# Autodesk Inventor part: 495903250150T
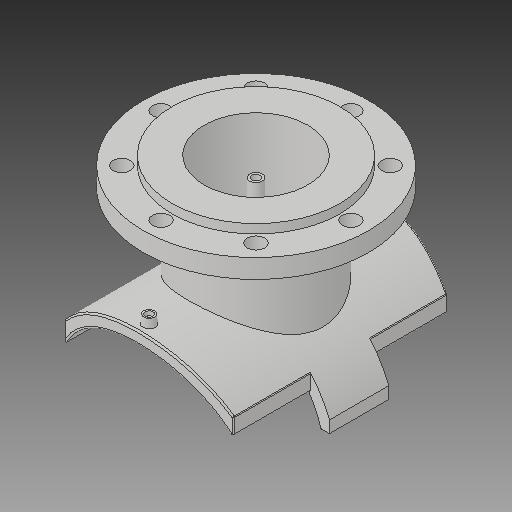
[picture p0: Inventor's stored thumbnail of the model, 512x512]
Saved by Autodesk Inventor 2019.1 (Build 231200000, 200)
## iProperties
Created: 2017-10
Part Number: 495903250150T
Material: Generic
Description: PLASSON FLANGED BRANCH SADDLE 250x150
Document SubType Name: Modeling
Designer: KIM
Mass: 2339.99 g
Surface Area: 3251.55 cm^2
Volume: 2339.99 cm^3
Density: 1 g/cm^3
Appearance: Default
Author: KIM
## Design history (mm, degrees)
derived "495904_495903.ipt"
feature "Solid1::495904_495903.ipt"
feature "Solid2::495904_495903.ipt"
tag "TaggingFeature1"
body "Solid1"
other parameters: "d1" = 15, "d2" = 213.3, "d4" = 0, "d6" = 75, "d7" = 0, "d12" = 150.6, "d13" = 14, "d14" = 135, "d16" = 5 deg, "d18" = 4, "d19" = 14, "d20" = 0, "d21" = 3, "d22" = 0, "d23" = 272, "d36" = 135, "d38" = 0, "d39" = 2, "d41" = 131, "d42" = 212, "d43" = 285, "d44" = 105.6, "d46" = 169.6, "d47" = 16, "d48" = 10.4, "d49" = 92.4, "d51" = 255, "d53" = 0, "d54" = 22, "d57" = 0, "d59" = 360 deg, "d61" = 24, "d63" = 0, "d66" = 132, "d67" = 15, "d68" = 66, "d70" = 0, "d71" = 2, "d72" = 237, "d_1" = 212, "B_" = 237, "H_" = 132, "x_" = 15, "D_" = 16, "DN_" = 131, "D_1" = 285, "t_" = 24, "s_" = 22
